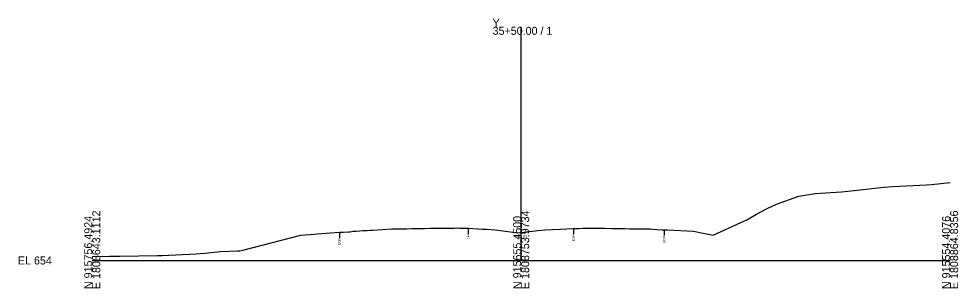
# Model space of a CAD drawing. Extents: x -26 to 3303, y -30 to 9580.
# Drawn here: x 1974.3 to 2302.8, y 5490.3 to 5584.5 of the extents above; entities that cross this region are included whole.
import ezdxf

# ---------------------------------------------------------------- set-up
doc = ezdxf.new("R2010")
doc.units = 0
for name, color, linetype in [('Exist Cross Section Cell', 7, 'Continuous'), ('Exist XS Center Line Elevation Label', 7, 'Continuous'), ('Exist XS Ground Line', 7, 'Continuous'), ('Old_Level_10', 7, 'Continuous')]:
    doc.layers.add(name, color=color, linetype=linetype)

msp = doc.modelspace()

# ---------------------------------------------------------------- linework, layer by layer
at = {"layer": 'Exist Cross Section Cell'}
for p, q in [((2150, 5500), (2150, 5581.73)), ((2000, 5500), (2150, 5500)), ((2150, 5500), (2300, 5500))]:
    msp.add_line(p, q, dxfattribs=at)
at = {"layer": 'Exist XS Ground Line'}
msp.add_lwpolyline([(2000, 5501.42), (2006.06, 5501.47), (2009.32, 5501.51), (2009.64, 5501.52), (2022.85, 5501.71), (2024.48, 5501.72), (2036.38, 5502.33), (2039.33, 5502.57), (2044.87, 5503.1), (2050.77, 5503.36), (2051.59, 5503.38), (2052.62, 5503.64), (2072.92, 5508.91), (2077.57, 5509.22), (2078.61, 5509.29), (2080.27, 5509.41), (2083.36, 5509.63), (2086.44, 5509.85), (2086.82, 5509.85), (2087.83, 5509.88), (2089.64, 5510.01), (2090.21, 5510.07), (2091.24, 5510.23), (2092.33, 5510.29), (2093.53, 5510.37), (2094.62, 5510.44), (2096.16, 5510.54), (2097.31, 5510.61), (2097.99, 5510.65), (2101.36, 5510.86), (2104.74, 5511.02), (2106.5, 5511.05), (2108.41, 5511.09), (2110.03, 5511.12), (2111.8, 5511.15), (2112.1, 5511.15), (2114.9, 5511.2), (2115.41, 5511.22), (2115.83, 5511.23), (2116.15, 5511.23), (2118.28, 5511.27), (2119.56, 5511.29), (2121.67, 5511.31), (2122.41, 5511.32), (2123.23, 5511.33), (2125.07, 5511.34), (2126.72, 5511.36), (2127.64, 5511.37), (2128.42, 5511.33), (2129.5, 5511.26), (2131.52, 5511.25), (2134.9, 5511.08), (2136.45, 5510.99), (2137.34, 5510.94), (2137.93, 5510.91), (2140.76, 5510.77), (2141.85, 5510.63), (2148.79, 5509.69), (2150, 5509.81), (2155.87, 5510.44), (2158.29, 5510.7), (2163.63, 5510.98), (2168.33, 5511.23), (2169.21, 5511.23), (2170.21, 5511.24), (2171.51, 5511.29), (2172.44, 5511.33), (2172.83, 5511.32), (2173.71, 5511.31), (2175.18, 5511.29), (2175.82, 5511.28), (2179.14, 5511.25), (2181.69, 5511.21), (2182.65, 5511.2), (2184.17, 5511.17), (2185.95, 5511.15), (2186.33, 5511.14), (2187.87, 5511.13), (2189.32, 5511.12), (2190.03, 5511.11), (2192.7, 5511.07), (2193.2, 5511.06), (2193.73, 5511.05), (2195.06, 5511.03), (2195.94, 5511.01), (2197.5, 5510.86), (2199.31, 5510.76), (2199.98, 5510.74), (2201.01, 5510.69), (2210.31, 5510.25), (2213.61, 5509.54), (2217.1, 5508.85), (2226.77, 5513.23), (2228.91, 5514.25), (2232.32, 5516.15), (2235.99, 5518.16), (2239.34, 5519.73), (2247.16, 5522.53), (2252.87, 5523.48), (2262.01, 5524), (2266.4, 5524.47), (2276.85, 5525.6), (2279.93, 5525.92), (2291.7, 5526.51), (2293.46, 5526.61), (2300, 5527.24)], dxfattribs=at)
at = {"layer": 'Old_Level_10'}
for p, q in [((2086.44, 5509.85), (2086.44, 5507.8)), ((2131.52, 5511.25), (2131.52, 5509.2)), ((2168.33, 5511.23), (2168.33, 5509.18)), ((2199.98, 5510.74), (2199.98, 5508.69))]:
    msp.add_line(p, q, dxfattribs=at)

# ---------------------------------------------------------------- texts
at = {"layer": 'Exist Cross Section Cell'}
for s, p in [('Y', (2140, 5581.73)), ('35+50.00 / 1', (2140, 5578.93)), ('EL 654', (1974, 5498.6))]:
    msp.add_text(s, height=2.8, dxfattribs=at).set_placement(p)
for s, p in [('E 1808643.1112', (2002.8, 5490)), ('E 1808753.9734', (2152.8, 5490)), ('E 1808864.8356', (2302.8, 5490)), ('N 915756.4924', (2000, 5490)), ('N 915655.4500', (2150, 5490)), ('N 915554.4076', (2300, 5490))]:
    msp.add_text(s, height=2.8, rotation=90, dxfattribs=at).set_placement(p)
at = {"layer": 'Exist XS Center Line Elevation Label'}
msp.add_text('663.81', height=1, dxfattribs=at).set_placement((2148.04, 5507.81))
at = {"layer": 'Old_Level_10'}
for p in [(2086.83, 5505.41), (2131.92, 5506.8), (2168.73, 5506.78), (2200.37, 5506.29)]:
    msp.add_text('EOP', height=0.787, rotation=90, dxfattribs=at).set_placement(p)

doc.saveas('drawing.dxf')
